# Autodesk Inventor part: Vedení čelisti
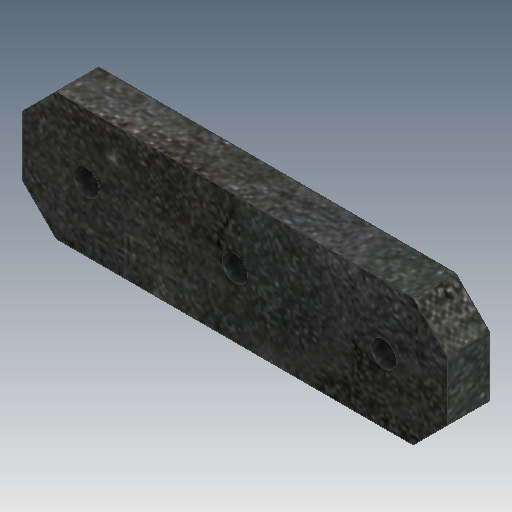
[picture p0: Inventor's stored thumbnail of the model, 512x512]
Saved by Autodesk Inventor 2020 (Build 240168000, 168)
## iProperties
Created: 2025-03
Part Number: Vedení čelisti
Material: Ocel
Document SubType Name: Modeling
Designer: doma
Density: 7.85 g/cm^3
Appearance: Plech
Mass: 218.793 g
Surface Area: 85.5239 cm^2
Volume: 27.8718 cm^3
Author: doma
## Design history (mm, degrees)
sketch "Náčrt1"
  geometry: L1 (-50, -15)-(50, -15); L2 (50, -15)-(50, 15); L3 (50, 15)-(-50, 15); L4 (-50, 15)-(-50, -15); L5 (-50, -15)-(50, 15); L6 (50, -15)-(-50, 15); C1 r 3 at (0, 0); C2 r 3 at (35, 0); C3 r 3 at (-35, 0); 1 further point
  constraints: 12 end point, 3 centre point, 2 midpoint, 2 parallel, 1 coincident, 1 horizontal, 1 perpendicular
  dimensions: "d0" = 100 distance of L3.end L2.end; "d1" = 30 distance of L2.end L1.end; "d4" = 6 diameter of C1; "d5" = 6 diameter of C2; "d6" = 6 diameter of C3; "d7" = 35 distance of point (0, 0) C3.centre; "d8" = 35 distance of C2.centre point (0, 0)
extrude "Vysunutí1" new body sketch "Náčrt1" distance "d2" = 10; taper "d3" = 0 deg
chamfer "Zkosení1" distance "d9" = 8; stored, may be unused: second distance "d10" = 2, angle "d11" = 45 deg
node "Těleso1"
